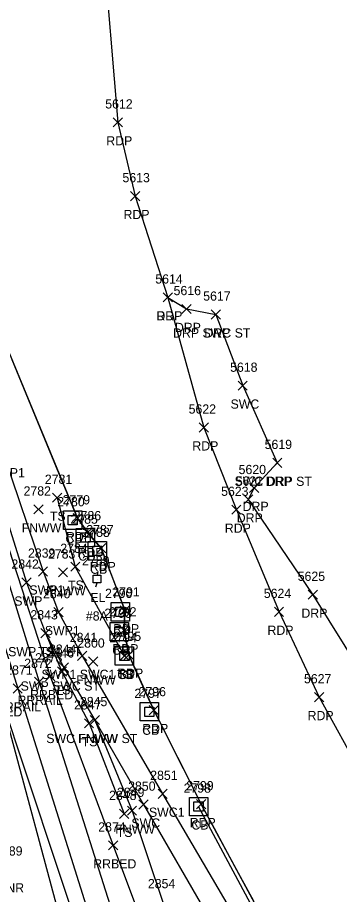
# Model space of a CAD drawing. Extents: x 1462668 to 1465147, y 550359 to 557351.
# Drawn here: x 1464324.5 to 1464394.4, y 553509.3 to 553699.4 of the extents above; entities that cross this region are included whole.
import ezdxf

# ---------------------------------------------------------------- set-up
doc = ezdxf.new("R2010")
doc.units = 0
for name, color, linetype in [('D_A', 7, 'Continuous'), ('D_I', 7, 'Continuous'), ('DS', 7, 'Continuous'), ('L_A', 7, 'Continuous'), ('L_I', 7, 'Continuous'), ('L_TIC', 7, 'Continuous'), ('LELB', 7, 'Continuous'), ('Level 6', 7, 'Continuous'), ('LFNC', 7, 'Continuous'), ('P_A', 7, 'Continuous'), ('P_I', 7, 'Continuous'), ('P_TIC', 7, 'Continuous'), ('PET', 7, 'Continuous'), ('R_A', 7, 'Continuous'), ('R_I', 7, 'Continuous'), ('R_TIC', 7, 'Continuous'), ('RC', 7, 'Continuous'), ('RDP', 7, 'Continuous'), ('RR', 7, 'Continuous'), ('RRB', 7, 'Continuous'), ('RSW', 7, 'Continuous'), ('U_A', 7, 'Continuous'), ('U_C', 7, 'Continuous'), ('U_I', 7, 'Continuous'), ('UEPT', 7, 'Continuous')]:
    doc.layers.add(name, color=color, linetype=linetype)

msp = doc.modelspace()

# ---------------------------------------------------------------- linework, layer by layer
at = {"layer": 'DS'}
for p, q in [((1464334.49, 553592.44), (1464338.49, 553592.44)), ((1464334.49, 553588.44), (1464334.49, 553592.44)), ((1464338.49, 553592.44), (1464338.49, 553588.44)), ((1464335.49, 553589.44), (1464335.49, 553591.44)), ((1464335.49, 553591.44), (1464337.49, 553591.44)), ((1464336.5, 553590.44), (1464336.5, 553590.44)), ((1464336.5, 553590.44), (1464336.5, 553590.44)), ((1464337.49, 553591.44), (1464337.49, 553589.44)), ((1464338.49, 553588.44), (1464334.49, 553588.44)), ((1464337.49, 553589.44), (1464335.49, 553589.44)), ((1464337.27, 553588.66), (1464341.27, 553588.66)), ((1464337.27, 553584.66), (1464337.27, 553588.66)), ((1464341.27, 553588.66), (1464341.27, 553584.66)), ((1464338.27, 553585.66), (1464338.27, 553587.66)), ((1464338.27, 553587.66), (1464340.27, 553587.66)), ((1464339.27, 553586.66), (1464339.27, 553586.66)), ((1464339.27, 553586.66), (1464339.27, 553586.66)), ((1464340.27, 553587.66), (1464340.27, 553585.66)), ((1464341.27, 553584.66), (1464337.27, 553584.66)), ((1464340.27, 553585.66), (1464338.27, 553585.66)), ((1464339.86, 553585.79), (1464343.86, 553585.79)), ((1464339.86, 553581.79), (1464339.86, 553585.79)), ((1464340.86, 553582.79), (1464340.86, 553584.79)), ((1464340.86, 553584.79), (1464342.86, 553584.79)), ((1464342.86, 553584.79), (1464342.86, 553582.79)), ((1464343.86, 553585.79), (1464343.86, 553581.79)), ((1464342.86, 553582.79), (1464340.86, 553582.79)), ((1464341.86, 553583.8), (1464341.86, 553583.8)), ((1464341.86, 553583.8), (1464341.86, 553583.8)), ((1464343.86, 553581.79), (1464339.86, 553581.79)), ((1464344.86, 553572.55), (1464348.86, 553572.55)), ((1464344.86, 553568.55), (1464344.86, 553572.55)), ((1464345.86, 553569.55), (1464345.86, 553571.55)), ((1464345.86, 553571.55), (1464347.86, 553571.55)), ((1464347.86, 553571.55), (1464347.86, 553569.55)), ((1464348.86, 553572.55), (1464348.86, 553568.55)), ((1464347.86, 553569.55), (1464345.86, 553569.55)), ((1464346.87, 553570.55), (1464346.87, 553570.55)), ((1464346.87, 553570.55), (1464346.87, 553570.55)), ((1464344.65, 553568.25), (1464348.65, 553568.25)), ((1464344.65, 553564.25), (1464344.65, 553568.25)), ((1464348.86, 553568.55), (1464344.86, 553568.55)), ((1464345.65, 553565.25), (1464345.65, 553567.25)), ((1464345.65, 553567.25), (1464347.65, 553567.25)), ((1464347.65, 553567.25), (1464347.65, 553565.25)), ((1464348.65, 553568.25), (1464348.65, 553564.25)), ((1464347.65, 553565.25), (1464345.65, 553565.25)), ((1464346.65, 553566.25), (1464346.65, 553566.25)), ((1464346.65, 553566.25), (1464346.65, 553566.25)), ((1464348.65, 553564.25), (1464344.65, 553564.25)), ((1464345.74, 553562.97), (1464349.74, 553562.97)), ((1464345.74, 553558.97), (1464345.74, 553562.97)), ((1464346.74, 553559.97), (1464346.74, 553561.97)), ((1464346.74, 553561.97), (1464348.74, 553561.97)), ((1464348.74, 553561.97), (1464348.74, 553559.97)), ((1464349.74, 553562.97), (1464349.74, 553558.97)), ((1464348.74, 553559.97), (1464346.74, 553559.97)), ((1464347.75, 553560.97), (1464347.75, 553560.97)), ((1464347.75, 553560.97), (1464347.75, 553560.97)), ((1464349.74, 553558.97), (1464345.74, 553558.97)), ((1464351.15, 553550.88), (1464355.15, 553550.88)), ((1464351.15, 553546.88), (1464351.15, 553550.88)), ((1464355.15, 553550.88), (1464355.15, 553546.88)), ((1464352.15, 553547.88), (1464352.15, 553549.88)), ((1464352.15, 553549.88), (1464354.15, 553549.88)), ((1464353.16, 553548.88), (1464353.16, 553548.88)), ((1464353.16, 553548.88), (1464353.16, 553548.88)), ((1464354.15, 553549.88), (1464354.15, 553547.88)), ((1464355.15, 553546.88), (1464351.15, 553546.88)), ((1464354.15, 553547.88), (1464352.15, 553547.88)), ((1464361.83, 553530.32), (1464365.83, 553530.32)), ((1464361.83, 553526.32), (1464361.83, 553530.32)), ((1464362.83, 553527.32), (1464362.83, 553529.32)), ((1464362.83, 553529.32), (1464364.83, 553529.32)), ((1464364.83, 553529.32), (1464364.83, 553527.32)), ((1464365.83, 553530.32), (1464365.83, 553526.32)), ((1464364.83, 553527.32), (1464362.83, 553527.32)), ((1464363.84, 553528.33), (1464363.84, 553528.33)), ((1464363.84, 553528.33), (1464363.84, 553528.33)), ((1464365.83, 553526.32), (1464361.83, 553526.32))]:
    msp.add_line(p, q, dxfattribs=at)
at = {"layer": 'L_TIC'}
for points in [[(1464332.15, 553594.31), (1464334.15, 553596.31)], [(1464334.15, 553594.31), (1464332.15, 553596.31)], [(1464328.09, 553591.77), (1464330.09, 553593.77)], [(1464330.09, 553591.77), (1464328.09, 553593.77)], [(1464336.07, 553579.34), (1464338.07, 553581.34)], [(1464338.07, 553579.34), (1464336.07, 553581.34)], [(1464333.39, 553578.11), (1464335.39, 553580.11)], [(1464335.39, 553578.11), (1464333.39, 553580.11)], [(1464329.58, 553564.91), (1464331.58, 553566.91)], [(1464331.58, 553564.91), (1464329.58, 553566.91)], [(1464346.75, 553559.97), (1464348.75, 553561.97)], [(1464348.75, 553559.97), (1464346.75, 553561.97)], [(1464339.93, 553558.79), (1464341.93, 553560.79)], [(1464341.93, 553558.79), (1464339.93, 553560.79)], [(1464333.17, 553556.63), (1464335.17, 553558.63)], [(1464335.17, 553556.63), (1464333.17, 553558.63)], [(1464340.33, 553546.09), (1464342.33, 553548.09)], [(1464342.33, 553546.09), (1464340.33, 553548.09)], [(1464339.05, 553545.38), (1464341.05, 553547.38)], [(1464341.05, 553545.38), (1464339.05, 553547.38)], [(1464346.66, 553525.74), (1464348.66, 553527.74)], [(1464348.66, 553525.74), (1464346.66, 553527.74)], [(1464348.39, 553526.42), (1464350.39, 553528.42)], [(1464350.39, 553526.42), (1464348.39, 553528.42)]]:
    msp.add_lwpolyline(points, dxfattribs=at)
at = {"layer": 'LELB'}
for points in [[(1464333.15, 553595.31), (1464337.07, 553580.34), (1464347.75, 553560.97)], [(1464330.58, 553565.91), (1464334.17, 553557.63), (1464340.05, 553546.38), (1464347.66, 553526.74)], [(1464320.57, 553552.86), (1464335.76, 553496.58), (1464351.01, 553439.58), (1464352, 553433.56), (1464356.91, 553435.89), (1464366.09, 553404.9), (1464375.79, 553365.63), (1464378.91, 553354.3), (1464392.5, 553314.3), (1464410.74, 553264.08), (1464424.65, 553220.18), (1464446.71, 553164.77), (1464462.56, 553121.26), (1464478.7, 553079.34), (1464487.04, 553051.03), (1464509.44, 553004.95), (1464519.17, 552979.76), (1464533.37, 552948.39), (1464548.85, 552915.73), (1464568.29, 552875.06), (1464587.07, 552834.38)]]:
    msp.add_lwpolyline(points, dxfattribs=at)
at = {"layer": 'Level 6'}
msp.add_lwpolyline([(1464375.81, 553507.78), (1464372.97, 553513.05), (1464370.12, 553518.32), (1464367.27, 553523.59), (1464364.42, 553528.85), (1464361.85, 553533.95), (1464359.27, 553539.05), (1464356.69, 553544.15), (1464354.12, 553549.25), (1464351.4, 553555.25), (1464348.68, 553561.24), (1464347.66, 553566.55), (1464347.8, 553570.88), (1464345.26, 553577.63), (1464342.71, 553584.38), (1464340.04, 553587.42), (1464337.57, 553590.85), (1464335.54, 553595.75), (1464333.51, 553600.65), (1464331.47, 553605.56), (1464329.44, 553610.46), (1464327.41, 553615.36), (1464325.37, 553620.27), (1464323.34, 553625.17)], dxfattribs=at)
at = {"layer": 'LFNC'}
msp.add_lwpolyline([(1464341.33, 553547.09), (1464349.39, 553527.42), (1464356.09, 553507.61), (1464365.08, 553479.7), (1464375.75, 553446.95), (1464383.68, 553420.52), (1464385.8, 553413.38)], dxfattribs=at)
at = {"layer": 'P_TIC'}
for points in [[(1464345.31, 553675.71), (1464347.31, 553677.71)], [(1464347.31, 553675.71), (1464345.31, 553677.71)], [(1464349.05, 553659.72), (1464351.05, 553661.72)], [(1464351.05, 553659.72), (1464349.05, 553661.72)], [(1464356.18, 553637.75), (1464358.18, 553639.75)], [(1464358.18, 553637.75), (1464356.18, 553639.75)], [(1464363.99, 553609.54), (1464365.99, 553611.54)], [(1464365.99, 553609.54), (1464363.99, 553611.54)], [(1464371.04, 553591.7), (1464373.04, 553593.7)], [(1464373.04, 553591.7), (1464371.04, 553593.7)], [(1464336.57, 553589.85), (1464338.57, 553591.85)], [(1464338.57, 553589.85), (1464336.57, 553591.85)], [(1464339.04, 553586.42), (1464341.04, 553588.42)], [(1464341.04, 553586.42), (1464339.04, 553588.42)], [(1464341.71, 553583.38), (1464343.71, 553585.38)], [(1464343.71, 553583.38), (1464341.71, 553585.38)], [(1464346.8, 553569.88), (1464348.8, 553571.88)], [(1464348.8, 553569.88), (1464346.8, 553571.88)], [(1464380.31, 553569.56), (1464382.31, 553571.56)], [(1464382.31, 553569.56), (1464380.31, 553571.56)], [(1464346.66, 553565.55), (1464348.66, 553567.55)], [(1464348.66, 553565.55), (1464346.66, 553567.55)], [(1464347.68, 553560.24), (1464349.68, 553562.24)], [(1464349.68, 553560.24), (1464347.68, 553562.24)], [(1464389.03, 553551.05), (1464391.03, 553553.05)], [(1464391.03, 553551.05), (1464389.03, 553553.05)], [(1464353.12, 553548.25), (1464355.12, 553550.25)], [(1464355.12, 553548.25), (1464353.12, 553550.25)], [(1464363.42, 553527.85), (1464365.42, 553529.85)], [(1464365.42, 553527.85), (1464363.42, 553529.85)]]:
    msp.add_lwpolyline(points, dxfattribs=at)
at = {"layer": 'PET'}
for points in [[(1464351.13, 553819.74), (1464346.72, 553799.45), (1464343.26, 553780.19), (1464341.6, 553758.02), (1464341.2, 553735.77), (1464343.02, 553715.47), (1464346.31, 553676.71), (1464350.05, 553660.72), (1464357.18, 553638.75), (1464364.99, 553610.54), (1464372.04, 553592.7), (1464381.31, 553570.56), (1464390.03, 553552.05), (1464402.47, 553529.5), (1464420.49, 553495.97)], [(1464308.19, 553737.4), (1464307.88, 553713.41), (1464308.79, 553693.79), (1464309.96, 553678.15), (1464314.44, 553652.47), (1464321.31, 553630.07), (1464337.57, 553590.85), (1464340.04, 553587.42), (1464342.71, 553584.38), (1464347.8, 553570.88), (1464347.66, 553566.55), (1464348.68, 553561.24), (1464354.12, 553549.25), (1464364.42, 553528.85)], [(1464387.21, 553486.72), (1464364.42, 553528.85)]]:
    msp.add_lwpolyline(points, dxfattribs=at)
at = {"layer": 'R_TIC'}
for points in [[(1464356.18, 553637.75), (1464358.18, 553639.75)], [(1464358.18, 553637.75), (1464356.18, 553639.75)], [(1464360.21, 553635.23), (1464362.21, 553637.23)], [(1464362.21, 553635.23), (1464360.21, 553637.23)], [(1464366.58, 553634.04), (1464368.58, 553636.04)], [(1464368.58, 553634.04), (1464366.58, 553636.04)], [(1464366.58, 553634.04), (1464368.58, 553636.04)], [(1464368.58, 553634.04), (1464366.58, 553636.04)], [(1464372.42, 553618.61), (1464374.42, 553620.61)], [(1464374.42, 553618.61), (1464372.42, 553620.61)], [(1464379.93, 553601.87), (1464381.93, 553603.87)], [(1464381.93, 553601.87), (1464379.93, 553603.87)], [(1464379.93, 553601.87), (1464381.93, 553603.87)], [(1464381.93, 553601.87), (1464379.93, 553603.87)], [(1464374.93, 553596.42), (1464376.93, 553598.42)], [(1464376.93, 553596.42), (1464374.93, 553598.42)], [(1464373.63, 553593.93), (1464375.63, 553595.93)], [(1464375.63, 553593.93), (1464373.63, 553595.93)], [(1464329.06, 553578.3), (1464331.06, 553580.3)], [(1464331.06, 553578.3), (1464329.06, 553580.3)], [(1464325.46, 553575.9), (1464327.46, 553577.9)], [(1464327.46, 553575.9), (1464325.46, 553577.9)], [(1464387.67, 553573.27), (1464389.67, 553575.27)], [(1464389.67, 553573.27), (1464387.67, 553575.27)], [(1464332.41, 553569.49), (1464334.41, 553571.49)], [(1464334.41, 553569.49), (1464332.41, 553571.49)], [(1464329.58, 553564.91), (1464331.58, 553566.91)], [(1464331.58, 553564.91), (1464329.58, 553566.91)], [(1464337.56, 553560), (1464339.56, 553562)], [(1464339.56, 553560), (1464337.56, 553562)], [(1464337.56, 553560), (1464339.56, 553562)], [(1464339.56, 553560), (1464337.56, 553562)], [(1464333.61, 553557.46), (1464335.61, 553559.46)], [(1464335.61, 553557.46), (1464333.61, 553559.46)], [(1464333.61, 553557.46), (1464335.61, 553559.46)], [(1464335.61, 553557.46), (1464333.61, 553559.46)], [(1464330.59, 553555.58), (1464332.59, 553557.58)], [(1464332.59, 553555.58), (1464330.59, 553557.58)], [(1464328.23, 553554.38), (1464330.23, 553556.38)], [(1464330.23, 553554.38), (1464328.23, 553556.38)], [(1464323.56, 553552.94), (1464325.56, 553554.94)], [(1464325.56, 553552.94), (1464323.56, 553554.94)], [(1464340.33, 553546.09), (1464342.33, 553548.09)], [(1464342.33, 553546.09), (1464340.33, 553548.09)], [(1464355.03, 553530.1), (1464357.03, 553532.1)], [(1464357.03, 553530.1), (1464355.03, 553532.1)], [(1464350.89, 553527.75), (1464352.89, 553529.75)], [(1464352.89, 553527.75), (1464350.89, 553529.75)], [(1464344.31, 553518.91), (1464346.31, 553520.91)], [(1464346.31, 553518.91), (1464344.31, 553520.91)]]:
    msp.add_lwpolyline(points, dxfattribs=at)
at = {"layer": 'RC'}
msp.add_lwpolyline([(1464386.39, 553486.27), (1464363.84, 553528.33)], dxfattribs=at)
at = {"layer": 'RDP'}
for points in [[(1464357.18, 553638.75), (1464361.21, 553636.23), (1464367.58, 553635.04)], [(1464380.93, 553602.87), (1464375.93, 553597.42), (1464374.63, 553594.93), (1464388.67, 553574.27), (1464399.1, 553557.51), (1464410.54, 553536.87), (1464418.41, 553537.61), (1464422.73, 553536.41), (1464441.52, 553507.83), (1464427.09, 553498.51), (1464434.68, 553487.58), (1464449.65, 553495.47)]]:
    msp.add_lwpolyline(points, dxfattribs=at)
at = {"layer": 'RR'}
for points in [[(1464154.28, 554097.88), (1464165.91, 554060.67), (1464179.18, 554017.63), (1464192.39, 553975.37), (1464204.49, 553936.13), (1464218.06, 553892.73), (1464235.46, 553837.34), (1464253.11, 553781.21), (1464266.29, 553739.57), (1464273.1, 553717.55), (1464293.09, 553653.68), (1464309.88, 553600.87), (1464324.56, 553553.94), (1464342.17, 553498.07)], [(1464159.2, 554098.67), (1464170.62, 554062.01), (1464183.92, 554019.07), (1464196.89, 553977.39), (1464209.21, 553938.08), (1464222.64, 553894.36), (1464240.12, 553839.14), (1464257.79, 553782.62), (1464270.96, 553740.9), (1464277.93, 553719.15), (1464297.82, 553655.4), (1464314.57, 553602.42), (1464329.23, 553555.38), (1464346.96, 553499.53)]]:
    msp.add_lwpolyline(points, dxfattribs=at)
at = {"layer": 'RRB'}
for points in [[(1464151.79, 554097.77), (1464163.73, 554059.7), (1464177.17, 554017.63), (1464190.46, 553974.22), (1464202.51, 553935.73), (1464215.79, 553891.79), (1464232.83, 553836.51), (1464250.85, 553780.59), (1464262.35, 553738.51), (1464269.73, 553716.51), (1464275.24, 553698.12), (1464287.03, 553660.88), (1464293.5, 553639.16), (1464306.31, 553607.26), (1464308.6, 553599.83), (1464319.37, 553564.19), (1464320.57, 553552.86), (1464339.05, 553497.3)], [(1464161.71, 554099.45), (1464173.81, 554063.1), (1464186.02, 554019.88), (1464199.38, 553978.33), (1464209.4, 553949.71), (1464214.23, 553929.59), (1464224.65, 553895.04), (1464242.27, 553839.51), (1464259.34, 553783.49), (1464272.85, 553741.47), (1464279.49, 553719.79), (1464299.3, 553656.24), (1464316.44, 553603.18), (1464331.59, 553556.58), (1464345.31, 553519.91), (1464352.28, 553501.12)]]:
    msp.add_lwpolyline(points, dxfattribs=at)
at = {"layer": 'RSW'}
for points in [[(1464297.07, 553670.96), (1464301.06, 553671.34), (1464304.96, 553658.21), (1464321.49, 553604.72), (1464330.06, 553579.3), (1464333.41, 553570.49), (1464338.56, 553561)], [(1464297.07, 553670.96), (1464301.31, 553656.95), (1464318.09, 553603.62), (1464326.46, 553576.9), (1464330.58, 553565.91), (1464334.61, 553558.46)], [(1464367.58, 553635.04), (1464373.42, 553619.61), (1464380.93, 553602.87)], [(1464338.56, 553561), (1464356.03, 553531.1), (1464372.44, 553503.14)], [(1464334.61, 553558.46), (1464341.33, 553547.09), (1464351.89, 553528.75), (1464366.86, 553502.91), (1464379.55, 553481.92), (1464387.46, 553468.75)]]:
    msp.add_lwpolyline(points, dxfattribs=at)
at = {"layer": 'UEPT'}
for p, q in [((1464340.97, 553576.83), (1464340.97, 553578.5)), ((1464340.97, 553578.5), (1464342.64, 553578.5)), ((1464341.97, 553579.33), (1464341.81, 553578.5)), ((1464342.64, 553578.5), (1464342.64, 553576.83)), ((1464342.64, 553576.83), (1464340.97, 553576.83)), ((1464341.56, 553576), (1464341.81, 553576.83)), ((1464341.81, 553577.66), (1464341.81, 553577.66))]:
    msp.add_line(p, q, dxfattribs=at)

# ---------------------------------------------------------------- texts
at = {"layer": 'D_A'}
for p in [(1464334.93, 553585.44), (1464337.7, 553581.66), (1464340.3, 553578.8), (1464345.3, 553565.55), (1464345.09, 553561.25), (1464346.18, 553555.97), (1464351.59, 553543.88), (1464362.27, 553523.33)]:
    msp.add_text('CB', height=2, dxfattribs=at).set_placement(p)
at = {"layer": 'D_I'}
for s, p in [('2780', (1464333.15, 553593.44)), ('2785', (1464336.01, 553589.66)), ('2788', (1464338.6, 553586.8)), ('2790', (1464343.52, 553573.55)), ('2793', (1464343.39, 553569.25)), ('2794', (1464344.49, 553563.97)), ('2797', (1464349.9, 553551.88)), ('2798', (1464360.58, 553531.33))]:
    msp.add_text(s, height=2, dxfattribs=at).set_placement(p)
at = {"layer": 'L_A'}
for s, p in [('TS', (1464331.56, 553590.31)), ('FNWW', (1464325.43, 553587.77)), ('TS', (1464335.48, 553575.34)), ('FNWW', (1464330.73, 553574.11)), ('TS', (1464328.98, 553560.91)), ('TS', (1464346.16, 553555.97)), ('FNWW', (1464337.27, 553554.79)), ('TS', (1464332.57, 553552.63)), ('FNWW', (1464337.68, 553542.09)), ('TS', (1464338.46, 553541.38)), ('FNWW', (1464345.74, 553522.42)), ('TS', (1464346.07, 553521.74)), ('FNR', (1464320.45, 553509.69))]:
    msp.add_text(s, height=2, dxfattribs=at).set_placement(p)
at = {"layer": 'L_I'}
for s, p in [('2781', (1464330.45, 553598.31)), ('2782', (1464325.83, 553595.77)), ('2784', (1464333.81, 553583.34)), ('2783', (1464331.13, 553582.11)), ('2843', (1464327.32, 553568.91)), ('2794', (1464344.49, 553563.97)), ('2800', (1464337.5, 553562.79)), ('2846', (1464330.85, 553560.63)), ('2845', (1464338.07, 553550.09)), ('2847', (1464336.79, 553549.38)), ('2848', (1464344.4, 553529.74)), ('2849', (1464346.12, 553530.42)), ('2889', (1464319.65, 553517.69)), ('2854', (1464352.83, 553510.61)), ('2854', (1464352.83, 553510.61))]:
    msp.add_text(s, height=2, dxfattribs=at).set_placement(p)
at = {"layer": 'P_A'}
for p in [(1464343.79, 553671.71), (1464347.54, 553655.72), (1464354.67, 553633.75), (1464362.48, 553605.54), (1464369.53, 553587.7), (1464335.06, 553585.85), (1464337.53, 553582.42), (1464340.2, 553579.38), (1464345.29, 553565.88), (1464378.8, 553565.56), (1464345.14, 553561.55), (1464346.17, 553556.24), (1464387.51, 553547.05), (1464351.6, 553544.25), (1464361.91, 553523.85)]:
    msp.add_text('RDP', height=2, dxfattribs=at).set_placement(p)
at = {"layer": 'P_I'}
for s, p in [('5612', (1464343.57, 553679.71)), ('5613', (1464347.31, 553663.72)), ('5614', (1464354.44, 553641.75)), ('5622', (1464361.68, 553613.54)), ('5623', (1464368.73, 553595.7)), ('2779', (1464334.31, 553593.85)), ('2786', (1464336.73, 553590.42)), ('2787', (1464339.45, 553587.38)), ('2791', (1464345.11, 553573.88)), ('5624', (1464378, 553573.56)), ('2792', (1464344.4, 553569.55)), ('2795', (1464345.42, 553564.24)), ('5627', (1464386.72, 553555.05)), ('2796', (1464350.8, 553552.25)), ('2799', (1464361.15, 553531.85))]:
    msp.add_text(s, height=2, dxfattribs=at).set_placement(p)
at = {"layer": 'R_A'}
for s, p in [('DRP', (1464354.67, 553633.75)), ('DRP SWC ST', (1464358.3, 553630.04)), ('DRP', (1464358.7, 553631.23)), ('DRP', (1464365.07, 553630.04)), ('SWC', (1464370.78, 553614.61)), ('SWP1', (1464318.53, 553599.72)), ('SWC DRP ST', (1464371.65, 553597.87)), ('DRP', (1464378.42, 553597.87)), ('DRP', (1464373.41, 553592.42)), ('DRP', (1464372.12, 553589.93)), ('SWP1', (1464327.1, 553574.3)), ('SWP', (1464323.82, 553571.9)), ('DRP', (1464386.16, 553569.27)), ('SWP1', (1464330.45, 553565.49)), ('SWP TS1 ST', (1464322.49, 553560.91)), ('SWP1 SWC1 ST', (1464329.72, 553556)), ('SWP1 SWC1 ST', (1464329.72, 553556)), ('SWP SWC ST', (1464325.2, 553553.46)), ('SWP SWC ST', (1464325.2, 553553.46)), ('RRRAIL', (1464324.52, 553550.38)), ('RRBED', (1464327.24, 553551.58)), ('RRRAIL', (1464319.85, 553548.94)), ('RRBED', (1464316.21, 553547.86)), ('SWC FNWW ST', (1464330.77, 553542.09)), ('SWC1', (1464353.06, 553526.1)), ('SWC', (1464349.25, 553523.75)), ('RRBED', (1464340.96, 553514.91))]:
    msp.add_text(s, height=2, dxfattribs=at).set_placement(p)
at = {"layer": 'R_I'}
for s, p in [('5614', (1464354.44, 553641.75)), ('5616', (1464358.41, 553639.23)), ('5617', (1464364.84, 553638.04)), ('5617', (1464364.84, 553638.04)), ('5618', (1464370.68, 553622.61)), ('5619', (1464378.18, 553605.87)), ('5619', (1464378.18, 553605.87)), ('5620', (1464372.53, 553600.42)), ('5621', (1464371.89, 553597.93)), ('2839', (1464326.79, 553582.3)), ('2842', (1464323.2, 553579.9)), ('5625', (1464385.36, 553577.27)), ('2840', (1464330.06, 553573.49)), ('2843', (1464327.32, 553568.91)), ('2841', (1464335.87, 553564)), ('2841', (1464335.87, 553564)), ('2844', (1464331.35, 553561.46)), ('2844', (1464331.35, 553561.46)), ('2873', (1464328.33, 553559.58)), ('2872', (1464325.97, 553558.38)), ('2871', (1464321.86, 553556.94)), ('2845', (1464338.07, 553550.09)), ('2851', (1464353.33, 553534.1)), ('2850', (1464348.54, 553531.75)), ('2874', (1464342.05, 553522.91))]:
    msp.add_text(s, height=2, dxfattribs=at).set_placement(p)
at = {"layer": 'U_A'}
msp.add_text('EL', height=2, dxfattribs=at).set_placement((1464340.34, 553572.66))
at = {"layer": 'U_C'}
msp.add_text('#8A', height=2, dxfattribs=at).set_placement((1464339.36, 553568.66))
at = {"layer": 'U_I'}
msp.add_text('2789', height=2, dxfattribs=at).set_placement((1464338.54, 553580.66))

doc.saveas('drawing.dxf')
